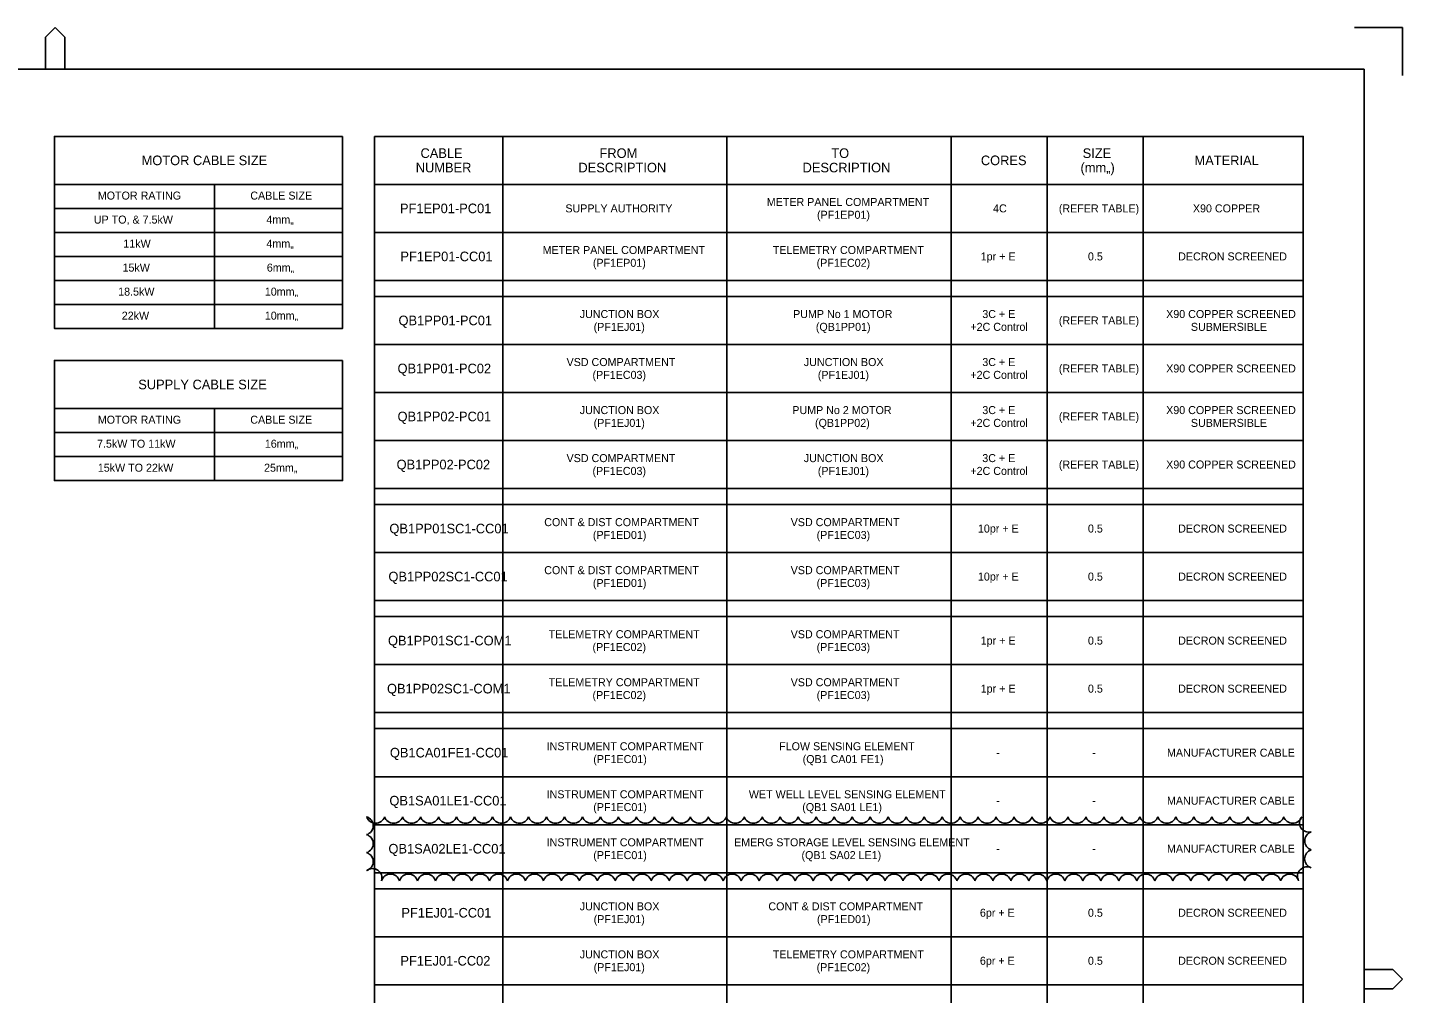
# Model space of a CAD drawing. Extents: x 0 to 841, y 0 to 594.
# Drawn here: x 411.6 to 841, y 292.3 to 594 of the extents above; entities that cross this region are included whole.
import ezdxf

# ---------------------------------------------------------------- set-up
doc = ezdxf.new("R2010")
doc.units = 0
for name, color, linetype in [('A1BORDER', 7, 'Continuous'), ('Default', 7, 'Continuous'), ('INSTALLED', 7, 'Continuous'), ('Level 1', 7, 'Continuous')]:
    doc.layers.add(name, color=color, linetype=linetype)

msp = doc.modelspace()

# ---------------------------------------------------------------- linework, layer by layer
at = {"layer": 'A1BORDER'}
for p, q in [((417.19, 591), (420.19, 594)), ((423.19, 591), (420.19, 594)), ((826, 594), (841, 594)), ((841, 579), (841, 594)), ((417.19, 581), (417.19, 591)), ((423.19, 581), (423.19, 591)), ((28, 581), (829, 581)), ((829, 581), (829, 15)), ((829, 299.76), (838, 299.76)), ((838, 299.76), (841, 296.76)), ((838, 293.76), (841, 296.76)), ((829, 293.76), (838, 293.76))]:
    msp.add_line(p, q, dxfattribs=at)
at = {"layer": 'Default'}
for p, q in [((420, 545), (510, 545)), ((470, 500), (470, 545)), ((420, 537.5), (510, 537.5)), ((420, 530), (510, 530)), ((420, 522.5), (510, 522.5)), ((420, 515), (510, 515)), ((420, 507.5), (510, 507.5)), ((420, 475), (510, 475)), ((470, 452.5), (470, 475)), ((420, 467.5), (510, 467.5)), ((420, 460), (510, 460))]:
    msp.add_line(p, q, dxfattribs=at)
for points in [[(510, 560), (420, 560), (420, 500), (510, 500)], [(510, 490), (420, 490), (420, 452.5), (510, 452.5)]]:
    msp.add_lwpolyline(points, close=True, dxfattribs=at)
at = {"layer": 'INSTALLED'}
for p, q in [((560, 560), (560, 190)), ((630, 560), (630, 190)), ((700, 560), (700, 190)), ((730, 560), (730, 190)), ((760, 560), (760, 190)), ((520, 545), (810, 545)), ((520, 530), (810, 530)), ((520, 515), (810, 515)), ((520, 510), (810, 510)), ((520, 495), (810, 495)), ((520, 480), (810, 480)), ((520, 465), (810, 465)), ((520, 450), (810, 450)), ((520, 445), (810, 445)), ((520, 430), (810, 430)), ((520, 415), (810, 415)), ((520, 410), (810, 410)), ((520, 395), (810, 395)), ((520, 380), (810, 380)), ((520, 375), (810, 375)), ((520, 360), (810, 360)), ((520, 345), (810, 345)), ((520, 330), (810, 330)), ((520, 325), (810, 325)), ((520, 310), (810, 310)), ((520, 295), (810, 295))]:
    msp.add_line(p, q, dxfattribs=at)
msp.add_lwpolyline([(520, 560), (810, 560), (810, 190), (520, 190)], close=True, dxfattribs=at)
at = {"layer": 'Level 1'}
for centre, radius, start, end in [((520.31, 348.39), 2.94, 197.5, 342.5), ((516.61, 344.69), 2.94, 287.5, 72.5), ((525.92, 348.39), 2.94, 197.5, 342.5), ((531.54, 348.39), 2.94, 197.5, 342.5), ((537.16, 348.39), 2.94, 197.5, 342.5), ((542.77, 348.39), 2.94, 197.5, 342.5), ((548.39, 348.39), 2.94, 197.5, 342.5), ((554, 348.39), 2.94, 197.5, 342.5), ((559.62, 348.39), 2.94, 197.5, 342.5), ((565.24, 348.39), 2.94, 197.5, 342.5), ((570.85, 348.39), 2.94, 197.5, 342.5), ((576.47, 348.39), 2.94, 197.5, 342.5), ((582.08, 348.39), 2.94, 197.5, 342.5), ((587.7, 348.39), 2.94, 197.5, 342.5), ((593.32, 348.39), 2.94, 197.5, 342.5), ((598.93, 348.39), 2.94, 197.5, 342.5), ((604.55, 348.39), 2.94, 197.5, 342.5), ((610.16, 348.39), 2.94, 197.5, 342.5), ((615.78, 348.39), 2.94, 197.5, 342.5), ((621.4, 348.39), 2.94, 197.5, 342.5), ((627.01, 348.39), 2.94, 197.5, 342.5), ((632.63, 348.39), 2.94, 197.5, 342.5), ((638.24, 348.39), 2.94, 197.5, 342.5), ((643.86, 348.39), 2.94, 197.5, 342.5), ((649.48, 348.39), 2.94, 197.5, 342.5), ((655.09, 348.39), 2.94, 197.5, 342.5), ((660.71, 348.39), 2.94, 197.5, 342.5), ((666.32, 348.39), 2.94, 197.5, 342.5), ((671.94, 348.39), 2.94, 197.5, 342.5), ((677.56, 348.39), 2.94, 197.5, 342.5), ((683.17, 348.39), 2.94, 197.5, 342.5), ((688.79, 348.39), 2.94, 197.5, 342.5), ((694.4, 348.39), 2.94, 197.5, 342.5), ((700.02, 348.39), 2.94, 197.5, 342.5), ((705.64, 348.39), 2.94, 197.5, 342.5), ((711.25, 348.39), 2.94, 197.5, 342.5), ((716.87, 348.39), 2.94, 197.5, 342.5), ((722.48, 348.39), 2.94, 197.5, 342.5), ((728.1, 348.39), 2.94, 197.5, 342.5), ((733.72, 348.39), 2.94, 197.5, 342.5), ((739.33, 348.39), 2.94, 197.5, 342.5), ((744.95, 348.39), 2.94, 197.5, 342.5), ((750.56, 348.39), 2.94, 197.5, 342.5), ((756.18, 348.39), 2.94, 197.5, 342.5), ((761.8, 348.39), 2.94, 197.5, 342.5), ((767.41, 348.39), 2.94, 197.5, 342.5), ((773.03, 348.39), 2.94, 197.5, 342.5), ((778.64, 348.39), 2.94, 197.5, 342.5), ((784.26, 348.39), 2.94, 197.5, 342.5), ((789.88, 348.39), 2.94, 197.5, 342.5), ((795.49, 348.39), 2.94, 197.5, 342.5), ((801.11, 348.39), 2.94, 197.5, 342.5), ((806.72, 348.39), 2.94, 197.5, 342.5), ((811.77, 345.59), 2.94, 139.4416, 284.4416), ((516.61, 339.08), 2.94, 287.5, 72.5), ((813.39, 339.93), 2.94, 107.5, 252.5), ((516.61, 333.46), 2.94, 287.5, 72.5), ((813.38, 334.32), 2.94, 107.5, 252.5), ((519.33, 328.34), 2.94, 343.3547, 128.3547), ((811.16, 328.88), 2.95, 63.0225, 208.0225), ((524.96, 326.61), 2.94, 17.5, 162.5), ((530.57, 326.61), 2.94, 17.5, 162.5), ((536.19, 326.61), 2.94, 17.5, 162.5), ((541.8, 326.61), 2.94, 17.5, 162.5), ((547.42, 326.61), 2.94, 17.5, 162.5), ((553.04, 326.61), 2.94, 17.5, 162.5), ((558.65, 326.61), 2.94, 17.5, 162.5), ((564.27, 326.61), 2.94, 17.5, 162.5), ((569.88, 326.61), 2.94, 17.5, 162.5), ((575.5, 326.61), 2.94, 17.5, 162.5), ((581.12, 326.61), 2.94, 17.5, 162.5), ((586.73, 326.61), 2.94, 17.5, 162.5), ((592.35, 326.61), 2.94, 17.5, 162.5), ((597.96, 326.61), 2.94, 17.5, 162.5), ((603.58, 326.61), 2.94, 17.5, 162.5), ((609.2, 326.61), 2.94, 17.5, 162.5), ((614.81, 326.61), 2.94, 17.5, 162.5), ((620.43, 326.61), 2.94, 17.5, 162.5), ((626.04, 326.61), 2.94, 17.5, 162.5), ((631.66, 326.61), 2.94, 17.5, 162.5), ((637.28, 326.61), 2.94, 17.5, 162.5), ((642.89, 326.61), 2.94, 17.5, 162.5), ((648.51, 326.61), 2.94, 17.5, 162.5), ((654.12, 326.61), 2.94, 17.5, 162.5), ((659.74, 326.61), 2.94, 17.5, 162.5), ((665.36, 326.61), 2.94, 17.5, 162.5), ((670.97, 326.61), 2.94, 17.5, 162.5), ((676.59, 326.61), 2.94, 17.5, 162.5), ((682.2, 326.61), 2.94, 17.5, 162.5), ((687.82, 326.61), 2.94, 17.5, 162.5), ((693.44, 326.61), 2.94, 17.5, 162.5), ((699.05, 326.61), 2.94, 17.5, 162.5), ((704.67, 326.61), 2.94, 17.5, 162.5), ((710.28, 326.61), 2.94, 17.5, 162.5), ((715.9, 326.61), 2.94, 17.5, 162.5), ((721.52, 326.61), 2.94, 17.5, 162.5), ((727.13, 326.61), 2.94, 17.5, 162.5), ((732.75, 326.61), 2.94, 17.5, 162.5), ((738.36, 326.61), 2.94, 17.5, 162.5), ((743.98, 326.61), 2.94, 17.5, 162.5), ((749.6, 326.61), 2.94, 17.5, 162.5), ((755.21, 326.61), 2.94, 17.5, 162.5), ((760.83, 326.61), 2.94, 17.5, 162.5), ((766.44, 326.61), 2.94, 17.5, 162.5), ((772.06, 326.61), 2.94, 17.5, 162.5), ((777.68, 326.61), 2.94, 17.5, 162.5), ((783.29, 326.61), 2.94, 17.5, 162.5), ((788.91, 326.61), 2.94, 17.5, 162.5), ((794.52, 326.61), 2.94, 17.5, 162.5), ((800.14, 326.61), 2.94, 17.5, 162.5), ((805.76, 326.61), 2.94, 17.5, 162.5)]:
    msp.add_arc(centre, radius, start, end, dxfattribs=at)

# ---------------------------------------------------------------- texts
at = {"layer": 'INSTALLED'}
for s, height, p in [('MOTOR CABLE SIZE', 3, (447.22, 551)), ('CABLE', 3, (534.32, 553.25)), ('FROM', 3, (590.22, 553.25)), ('TO', 3, (662.61, 553.25)), ('CORES', 3, (709.32, 551)), ('SIZE', 3, (741.12, 553.25)), ('MATERIAL', 3, (776.04, 551)), ('NUMBER', 3, (532.83, 548.75)), ('DESCRIPTION', 3, (583.64, 548.75)), ('DESCRIPTION', 3, (653.64, 548.75)), ('(mm„)', 3, (740.44, 548.75)), ('MOTOR RATING', 2.5, (433.54, 540.25)), ('CABLE SIZE', 2.5, (481.16, 540.25)), ('PF1EP01-PC01', 3, (527.9, 536)), ('SUPPLY AUTHORITY', 2.5, (579.56, 536.25)), ('METER PANEL COMPARTMENT', 2.5, (642.46, 538.25)), ('(PF1EP01)', 2.5, (658.15, 534.25)), ('4C', 2.5, (713.13, 536.25)), ('(REFER TABLE)', 2.5, (733.67, 536.25)), ('X90 COPPER', 2.5, (775.54, 536.25)), ('UP TO, & 7.5kW', 2.5, (432.3, 532.75)), ('4mm„', 2.5, (486.2, 532.75)), ('11kW', 2.5, (441.51, 525.25)), ('4mm„', 2.5, (486.2, 525.25)), ('PF1EP01-CC01', 3, (528.05, 521)), ('METER PANEL COMPARTMENT', 2.5, (572.46, 523.25)), ('TELEMETRY COMPARTMENT', 2.5, (644.33, 523.25)), ('15kW', 2.5, (441.26, 517.75)), ('6mm„', 2.5, (486.33, 517.75)), ('(PF1EP01)', 2.5, (588.15, 519.25)), ('(PF1EC02)', 2.5, (658.03, 519.25)), ('1pr + E', 2.5, (709.27, 521.25)), ('0.5', 2.5, (742.76, 521.25)), ('DECRON SCREENED', 2.5, (770.93, 521.25)), ('18.5kW', 2.5, (439.9, 510.25)), ('10mm„', 2.5, (485.7, 510.25)), ('22kW', 2.5, (441.02, 502.75)), ('10mm„', 2.5, (485.7, 502.75)), ('QB1PP01-PC01', 3, (527.45, 501)), ('JUNCTION BOX', 2.5, (584.04, 503.25)), ('PUMP No 1 MOTOR', 2.5, (650.68, 503.25)), ('3C + E', 2.5, (709.77, 503.25)), ('(REFER TABLE)', 2.5, (733.67, 501.25)), ('X90 COPPER SCREENED', 2.5, (767.19, 503.25)), ('(PF1EJ01)', 2.5, (588.4, 499.25)), ('(QB1PP01)', 2.5, (657.78, 499.25)), ('+2C Control', 2.5, (706.04, 499.25)), ('SUBMERSIBLE', 2.5, (774.91, 499.25)), ('VSD COMPARTMENT', 2.5, (579.93, 488.25)), ('JUNCTION BOX', 2.5, (654.04, 488.25)), ('3C + E', 2.5, (709.77, 488.25)), ('QB1PP01-PC02', 3, (527.15, 486)), ('(PF1EC03)', 2.5, (588.03, 484.25)), ('(PF1EJ01)', 2.5, (658.4, 484.25)), ('+2C Control', 2.5, (706.04, 484.25)), ('(REFER TABLE)', 2.5, (733.67, 486.25)), ('X90 COPPER SCREENED', 2.5, (767.19, 486.25)), ('SUPPLY CABLE SIZE', 3, (446.17, 481)), ('MOTOR RATING', 2.5, (433.54, 470.25)), ('CABLE SIZE', 2.5, (481.16, 470.25)), ('QB1PP02-PC01', 3, (527.15, 471)), ('JUNCTION BOX', 2.5, (584.04, 473.25)), ('PUMP No 2 MOTOR', 2.5, (650.43, 473.25)), ('3C + E', 2.5, (709.77, 473.25)), ('(REFER TABLE)', 2.5, (733.67, 471.25)), ('X90 COPPER SCREENED', 2.5, (767.19, 473.25)), ('(PF1EJ01)', 2.5, (588.4, 469.25)), ('(QB1PP02)', 2.5, (657.53, 469.25)), ('+2C Control', 2.5, (706.04, 469.25)), ('SUBMERSIBLE', 2.5, (774.91, 469.25)), ('7.5kW TO 11kW', 2.5, (433.3, 462.75)), ('16mm„', 2.5, (485.7, 462.75)), ('VSD COMPARTMENT', 2.5, (579.93, 458.25)), ('JUNCTION BOX', 2.5, (654.04, 458.25)), ('3C + E', 2.5, (709.77, 458.25)), ('15kW TO 22kW', 2.5, (433.54, 455.25)), ('25mm„', 2.5, (485.46, 455.25)), ('QB1PP02-PC02', 3, (526.85, 456)), ('(PF1EC03)', 2.5, (588.03, 454.25)), ('(PF1EJ01)', 2.5, (658.4, 454.25)), ('+2C Control', 2.5, (706.04, 454.25)), ('(REFER TABLE)', 2.5, (733.67, 456.25)), ('X90 COPPER SCREENED', 2.5, (767.19, 456.25)), ('QB1PP01SC1-CC01', 3, (524.61, 436)), ('CONT & DIST COMPARTMENT', 2.5, (572.96, 438.25)), ('VSD COMPARTMENT', 2.5, (649.93, 438.25)), ('10pr + E', 2.5, (708.4, 436.25)), ('0.5', 2.5, (742.76, 436.25)), ('DECRON SCREENED', 2.5, (770.93, 436.25)), ('(PF1ED01)', 2.5, (588.15, 434.25)), ('(PF1EC03)', 2.5, (658.03, 434.25)), ('CONT & DIST COMPARTMENT', 2.5, (572.96, 423.25)), ('VSD COMPARTMENT', 2.5, (649.93, 423.25)), ('QB1PP02SC1-CC01', 3, (524.31, 421)), ('(PF1ED01)', 2.5, (588.15, 419.25)), ('(PF1EC03)', 2.5, (658.03, 419.25)), ('10pr + E', 2.5, (708.4, 421.25)), ('0.5', 2.5, (742.76, 421.25)), ('DECRON SCREENED', 2.5, (770.93, 421.25)), ('QB1PP01SC1-COM1', 3, (524.16, 401)), ('TELEMETRY COMPARTMENT', 2.5, (574.33, 403.25)), ('VSD COMPARTMENT', 2.5, (649.93, 403.25)), ('1pr + E', 2.5, (709.27, 401.25)), ('0.5', 2.5, (742.76, 401.25)), ('DECRON SCREENED', 2.5, (770.93, 401.25)), ('(PF1EC02)', 2.5, (588.03, 399.25)), ('(PF1EC03)', 2.5, (658.03, 399.25)), ('TELEMETRY COMPARTMENT', 2.5, (574.33, 388.25)), ('VSD COMPARTMENT', 2.5, (649.93, 388.25)), ('QB1PP02SC1-COM1', 3, (523.86, 386)), ('(PF1EC02)', 2.5, (588.03, 384.25)), ('(PF1EC03)', 2.5, (658.03, 384.25)), ('1pr + E', 2.5, (709.27, 386.25)), ('0.5', 2.5, (742.76, 386.25)), ('DECRON SCREENED', 2.5, (770.93, 386.25)), ('INSTRUMENT COMPARTMENT', 2.5, (573.71, 368.25)), ('FLOW SENSING ELEMENT', 2.5, (646.32, 368.25)), ('QB1CA01FE1-CC01', 3, (524.76, 366)), ('(PF1EC01)', 2.5, (588.28, 364.25)), ('(QB1 CA01 FE1)', 2.5, (653.67, 364.25)), ('-', 2.5, (714.13, 366.25)), ('-', 2.5, (744.13, 366.25)), ('MANUFACTURER CABLE', 2.5, (767.44, 366.25)), ('QB1SA01LE1-CC01', 3, (524.61, 351)), ('INSTRUMENT COMPARTMENT', 2.5, (573.71, 353.25)), ('WET WELL LEVEL SENSING ELEMENT', 2.5, (636.86, 353.25)), ('-', 2.5, (714.13, 351.25)), ('-', 2.5, (744.13, 351.25)), ('MANUFACTURER CABLE', 2.5, (767.44, 351.25)), ('(PF1EC01)', 2.5, (588.28, 349.25)), ('(QB1 SA01 LE1)', 2.5, (653.54, 349.25)), ('INSTRUMENT COMPARTMENT', 2.5, (573.71, 338.25)), ('EMERG STORAGE LEVEL SENSING ELEMENT', 2.5, (632.25, 338.25)), ('QB1SA02LE1-CC01', 3, (524.31, 336)), ('(PF1EC01)', 2.5, (588.28, 334.25)), ('(QB1 SA02 LE1)', 2.5, (653.3, 334.25)), ('-', 2.5, (714.13, 336.25)), ('-', 2.5, (744.13, 336.25)), ('MANUFACTURER CABLE', 2.5, (767.44, 336.25)), ('PF1EJ01-CC01', 3, (528.35, 316)), ('JUNCTION BOX', 2.5, (584.04, 318.25)), ('CONT & DIST COMPARTMENT', 2.5, (642.96, 318.25)), ('6pr + E', 2.5, (709.02, 316.25)), ('0.5', 2.5, (742.76, 316.25)), ('DECRON SCREENED', 2.5, (770.93, 316.25)), ('(PF1EJ01)', 2.5, (588.4, 314.25)), ('(PF1ED01)', 2.5, (658.15, 314.25)), ('JUNCTION BOX', 2.5, (584.04, 303.25)), ('TELEMETRY COMPARTMENT', 2.5, (644.33, 303.25)), ('PF1EJ01-CC02', 3, (528.05, 301)), ('(PF1EJ01)', 2.5, (588.4, 299.25)), ('(PF1EC02)', 2.5, (658.03, 299.25)), ('6pr + E', 2.5, (709.02, 301.25)), ('0.5', 2.5, (742.76, 301.25)), ('DECRON SCREENED', 2.5, (770.93, 301.25))]:
    msp.add_text(s, height=height, dxfattribs=at).set_placement(p)

doc.saveas('drawing.dxf')
